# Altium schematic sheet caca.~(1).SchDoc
size A4
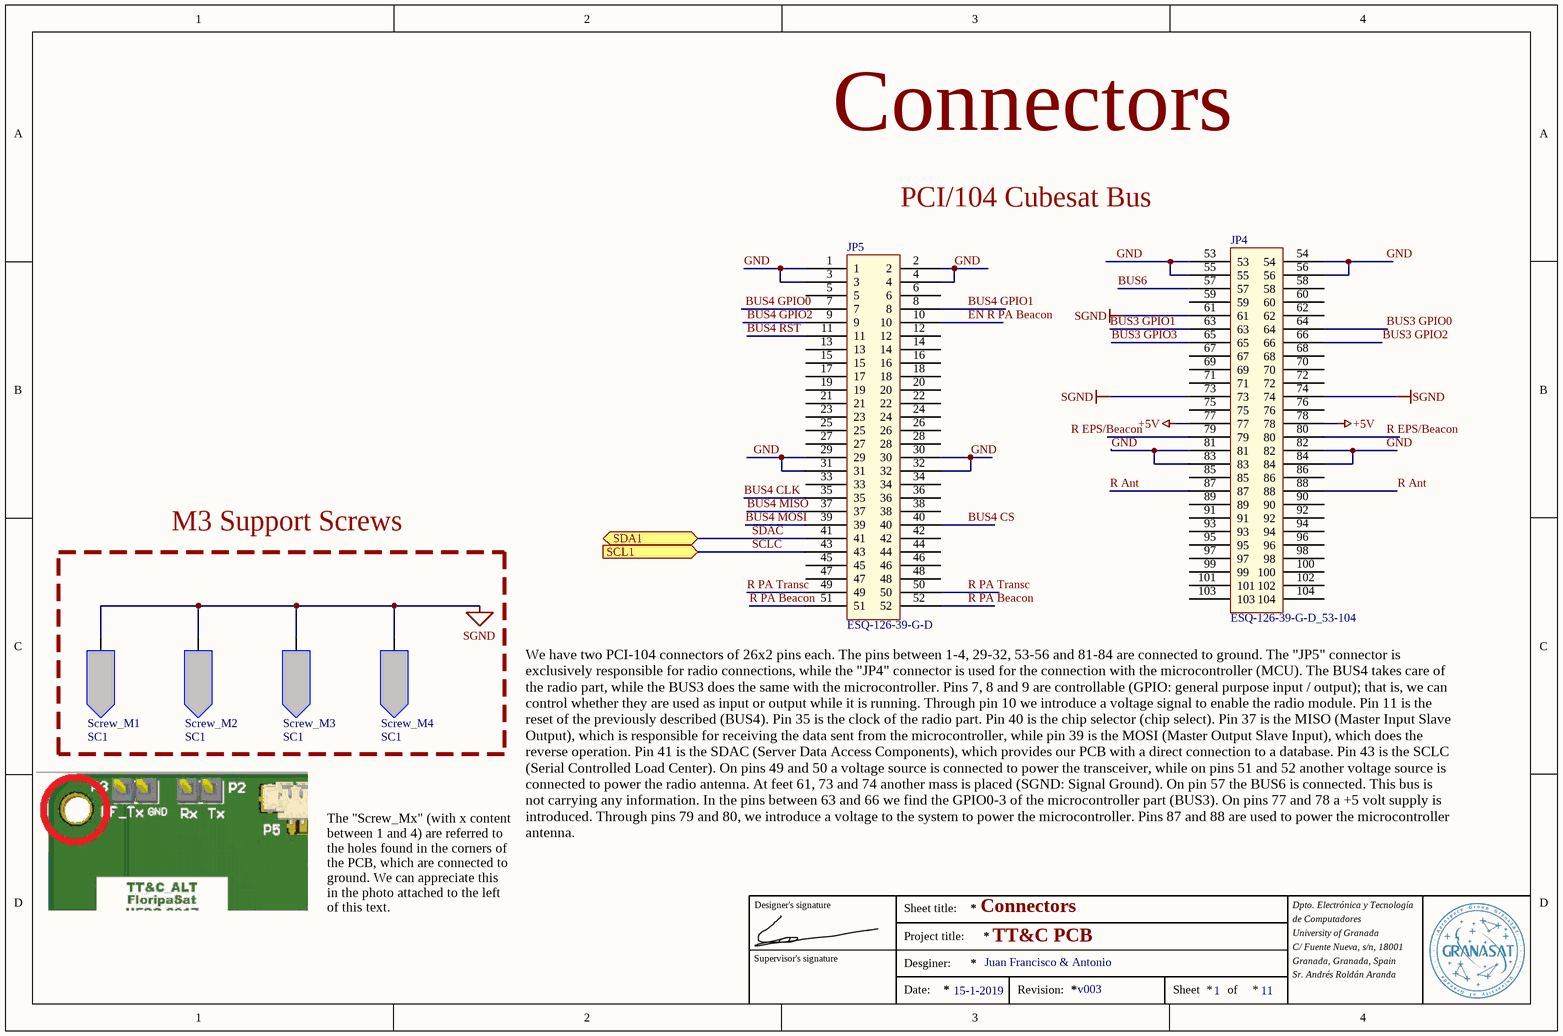
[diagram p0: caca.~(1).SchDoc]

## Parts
JP4  ESQ-126-39-G-D_53-104  [ESQ-126-39-G-D_53_104]
JP5  ESQ-126-39-G-D  [ESQ-126-39-G-D]
Screw_M1  SC1  [Screw_M3]
Screw_M2  SC1  [Screw_M3]
Screw_M3  SC1  [Screw_M3]
Screw_M4  SC1  [Screw_M3]

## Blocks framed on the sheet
M3 Support Screws: Screw_M1-Screw_M4

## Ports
SCL1 (in), SDA1 (bidir)

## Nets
+5V: JP4.77 JP4.78
SGND: JP4.61 JP4.73 JP4.74 Screw_M1.1 Screw_M2.1 Screw_M3.1 Screw_M4.1
BUS3 GPIO0: JP4.64
BUS3 GPIO1: JP4.63
BUS3 GPIO2: JP4.66
BUS3 GPIO3: JP4.65
BUS4 CLK: JP5.35
BUS4 CS: JP5.40
BUS4 GPIO0: JP5.7
BUS4 GPIO1: JP5.8
BUS4 GPIO2: JP5.9
BUS4 MISO: JP5.37
BUS4 MOSI: JP5.39
BUS4 RST: JP5.11
BUS6: JP4.57
EN R PA Beacon: JP5.10
GND: JP4.53 JP4.54 JP4.55 JP4.56 JP4.81 JP4.82 JP4.83 JP4.84 JP5.1 JP5.2 JP5.3 JP5.4 JP5.29 JP5.30 JP5.31 JP5.32
R Ant: JP4.87 JP4.88
R EPS/Beacon: JP4.80
R PA Beacon: JP5.51 JP5.52
R PA Transc: JP5.49 JP5.50
SCLC: JP5.43 ; port SCL1
SDAC: JP5.41 ; port SDA1

Not connected (* = marked no-connect by the designer): JP4 58 59 60 62 67 68 69 70 71 72 75 76 79 85 86 89 90 91 92 93 94 95 96 97 98 99 100 101 102 103 104; JP5 5 6 12 13 14 15 16 17 18 19 20 21 22 23 24 25 26 27 28 33 34 36 38 42 44 45 46 47 48

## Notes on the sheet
- Connectors
- PCI/104 Cubesat Bus
- We have two PCI-104 connectors of 26x2 pins each. The pins between 1-4, 29-32, 53-56 and 81-84 are connected to ground. The "JP5" connector is exclusively responsible for radio connections, while the "JP4" connector is used for the connection with the microcontroller (MCU). The BUS4 takes care of the radio part, while the BUS3 does the same with the microcontroller. Pins 7, 8 and 9 are controllable (GPIO: general purpose input / output); that is, we can control whether they are used as input or output while it is running. Through pin 10 we introduce a voltage signal to enable the radio module. Pin 11 is the reset of the previously described (BUS4). Pin 35 is the clock of the radio part. Pin 40 is the chip selector (chip select). Pin 37 is the MISO (Master Input Slave Output), which is responsible for receiving the data sent from the microcontroller, while pin 39 is the MOSI (Master Output Slave Input), which does the reverse operation. Pin 41 is the SDAC (Server Data Access Components), which provides our PCB with a direct connection to a database. Pin 43 is the SCLC (Serial Controlled Load Center). On pins 49 and 50 a voltage source is connected to power the transceiver, while on pins 51 and 52 another voltage source is connected to power the radio antenna. At feet 61, 73 and 74 another mass is placed (SGND: Signal Ground). On pin 57 the BUS6 is connected. This bus is not carrying any information. In the pins between 63 and 66 we find the GPIO0-3 of the microcontroller part (BUS3). On pins 77 and 78 a +5 volt supply is introduced. Through pins 79 and 80, we introduce a voltage to the system to power the microcontroller. Pins 87 and 88 are used to power the microcontroller antenna.
- The "Screw_Mx" (with x content between 1 and 4) are referred to the holes found in the corners of the PCB, which are connected to ground. We can appreciate this in the photo attached to the left of this text.
- Designer's signature
- Sheet title:
- Dpto. Electrónica y Tecnología
- de Computadores
- Supervisor's signature
- Project title:
- Desginer:
- Juan Francisco & Antonio
- TT&C PCB
- University of Granada
- C/ Fuente Nueva, s/n, 18001
- Granada, Granada, Spain
- Sr. Andrés Roldán Aranda
- Date:
- 15-1-2019
- Revision:
- v003
- Sheet
- 1
- of
- 11
- Labels drawn without touching a wire or pin: R EPS/Beacon

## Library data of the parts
JP4 = ESQ-126-39-G-D_53-104: Cubesat Header Connector; Shop: es.rs-online.com; Localización: Último cajón cajonera blanca entre Pablo y Luis; Reference: 254-6132
JP5 = ESQ-126-39-G-D: Cubesat Header Connector; Shop: es.rs-online.com; Localización: Último cajón cajonera blanca entre Pablo y Luis; Reference: 254-6132
Screw_M1-Screw_M4 = Screw_M3: Main CubeSAT bus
